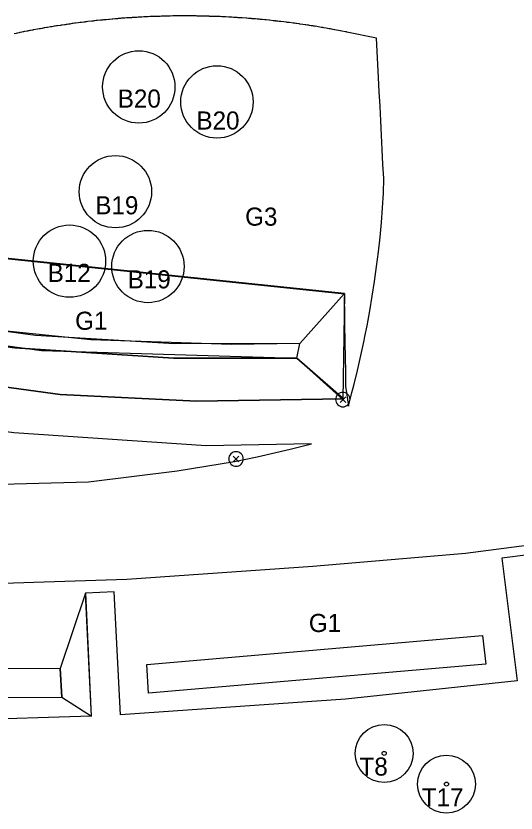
# Model space of a CAD drawing. Extents: x 0 to 512122, y 0 to 6212554.
# Drawn here: x 511565 to 511599.5, y 6211753.4 to 6211808.5 of the extents above; entities that cross this region are included whole.
import ezdxf

# ---------------------------------------------------------------- set-up
doc = ezdxf.new("R2010")
doc.units = 0
for name, color, linetype in [('_lights', 7, 'Continuous'), ('_LØ1', 7, 'Continuous'), ('L40 jord udlagt muld og grøft', 7, 'Continuous'), ('Skel', 7, 'Continuous'), ('TV_U_AFM_Symbl_Gul', 7, 'Continuous'), ('TV_U_LYS_Mastenummer', 7, 'Continuous')]:
    doc.layers.add(name, color=color, linetype=linetype)

# ---------------------------------------------------------------- blocks, each defined once
blk = doc.blocks.new('SOLITAIRE TREES')
at = {"layer": 'Skel'}
for radius in [2, 0.141]:
    blk.add_circle((0, 0), radius, dxfattribs=at)

msp = doc.modelspace()

# ---------------------------------------------------------------- linework, layer by layer
at = {"layer": '_lights'}
for p, q in [((511587.362, 6211782.207), (511587.756, 6211781.813)), ((511587.76, 6211782.211), (511587.366, 6211781.817)), ((511579.978, 6211778.1), (511580.372, 6211777.706)), ((511580.376, 6211778.104), (511579.982, 6211777.71))]:
    msp.add_line(p, q, dxfattribs=at)
for centre, start, end in [((511587.559, 6211782.01), 315.5636, 315), ((511587.559, 6211782.01), 315, 315.5636), ((511580.175, 6211777.903), 315.5636, 315), ((511580.175, 6211777.903), 315, 315.5636)]:
    msp.add_arc(centre, 0.5, start, end, dxfattribs=at)
at = {"layer": '_LØ1'}
msp.add_lwpolyline([(511539.066, 6211784.628), (511539.066, 6211776.31), (511557.102, 6211775.97), (511569.966, 6211776.326), (511576.1, 6211777.084), (511580.076, 6211777.733), (511581.646, 6211778.064), (511583.922, 6211778.583), (511584.736, 6211778.794), (511585.399, 6211778.957), (511578.113, 6211778.822), (511564.816, 6211779.711), (511553.308, 6211781.287), (511544.168, 6211783.234)], close=True, dxfattribs=at)
at = {"layer": 'L40 jord udlagt muld og grøft'}
msp.add_line((511587.73, 6211782.932), (511587.951, 6211781.556), dxfattribs=at)
for points in [[(511585.111, 6211807.892), (511584.999, 6211807.908), (511584.958, 6211807.914), (511584.793, 6211807.938), (511584.577, 6211807.969), (511584.573, 6211807.97), (511584.557, 6211807.972), (511584.519, 6211807.978), (511584.344, 6211808.003), (511584.301, 6211808.009), (511584.213, 6211808.023), (511584.137, 6211808.034), (511584.124, 6211808.036), (511583.86, 6211808.069), (511583.772, 6211808.079), (511583.717, 6211808.085), (511583.668, 6211808.091), (511583.478, 6211808.113), (511583.469, 6211808.114), (511583.279, 6211808.136), (511583.242, 6211808.14), (511583.163, 6211808.149), (511583.065, 6211808.161), (511582.973, 6211808.172), (511582.929, 6211808.177), (511582.929, 6211808.177), (511582.909, 6211808.179), (511582.861, 6211808.185), (511582.76, 6211808.197), (511582.74, 6211808.199), (511582.493, 6211808.228), (511582.489, 6211808.228), (511582.468, 6211808.23), (511582.247, 6211808.251), (511582.176, 6211808.258), (511582.005, 6211808.273), (511582.004, 6211808.273), (511581.96, 6211808.277), (511581.957, 6211808.277), (511581.854, 6211808.286), (511581.772, 6211808.293), (511581.729, 6211808.297), (511581.639, 6211808.305), (511581.512, 6211808.316), (511581.38, 6211808.327), (511581.355, 6211808.329), (511581.268, 6211808.337), (511581.248, 6211808.339), (511581.112, 6211808.35), (511581.097, 6211808.351), (511581.089, 6211808.352), (511581.077, 6211808.353), (511581.035, 6211808.357), (511580.919, 6211808.367), (511580.896, 6211808.369), (511580.877, 6211808.37), (511580.609, 6211808.391), (511580.586, 6211808.392), (511580.585, 6211808.392), (511580.576, 6211808.393), (511580.498, 6211808.397), (511580.381, 6211808.404), (511580.346, 6211808.406), (511580.342, 6211808.406), (511580.335, 6211808.407), (511580.333, 6211808.407), (511580.262, 6211808.411), (511580.068, 6211808.422), (511580.056, 6211808.423), (511580.005, 6211808.425), (511579.884, 6211808.432), (511579.791, 6211808.438), (511579.686, 6211808.444), (511579.472, 6211808.456), (511579.314, 6211808.465), (511579.276, 6211808.467), (511579.192, 6211808.472), (511579.088, 6211808.478), (511579.048, 6211808.48), (511579.037, 6211808.481), (511579.02, 6211808.481), (511578.997, 6211808.482), (511578.987, 6211808.482), (511578.92, 6211808.484), (511578.88, 6211808.485), (511578.769, 6211808.488), (511578.437, 6211808.497), (511578.426, 6211808.497), (511578.336, 6211808.5), (511578.311, 6211808.501), (511578.29, 6211808.501), (511578.276, 6211808.502), (511578.203, 6211808.504), (511578.159, 6211808.505), (511578.15, 6211808.505), (511578.08, 6211808.507), (511578.067, 6211808.507), (511578.001, 6211808.509), (511577.9, 6211808.512), (511577.846, 6211808.513), (511577.746, 6211808.516), (511577.71, 6211808.517), (511577.589, 6211808.52), (511577.516, 6211808.522), (511577.491, 6211808.523), (511577.41, 6211808.525), (511577.259, 6211808.526), (511577.167, 6211808.527), (511577.066, 6211808.527), (511576.943, 6211808.526), (511576.886, 6211808.526), (511576.777, 6211808.526), (511576.729, 6211808.526), (511576.719, 6211808.526), (511576.615, 6211808.525), (511576.561, 6211808.525), (511576.538, 6211808.525), (511576.493, 6211808.525), (511576.439, 6211808.525), (511576.215, 6211808.525), (511576.181, 6211808.525), (511575.89, 6211808.524), (511575.845, 6211808.524), (511575.821, 6211808.524), (511575.806, 6211808.524), (511575.805, 6211808.524), (511575.624, 6211808.522), (511575.583, 6211808.521), (511575.561, 6211808.52), (511575.506, 6211808.518), (511575.493, 6211808.518), (511575.472, 6211808.517), (511575.377, 6211808.514), (511575.163, 6211808.507), (511575.127, 6211808.506), (511575.074, 6211808.504), (511575.025, 6211808.503), (511574.941, 6211808.5), (511574.914, 6211808.5), (511574.908, 6211808.5), (511574.892, 6211808.499), (511574.865, 6211808.498), (511574.76, 6211808.495), (511574.651, 6211808.491), (511574.562, 6211808.488), (511574.432, 6211808.484), (511574.228, 6211808.478), (511574.104, 6211808.474), (511574.046, 6211808.472), (511574.038, 6211808.472), (511573.986, 6211808.469), (511573.859, 6211808.462), (511573.852, 6211808.462), (511573.811, 6211808.459), (511573.669, 6211808.451), (511573.595, 6211808.446), (511573.468, 6211808.438), (511573.429, 6211808.436), (511573.402, 6211808.434), (511573.325, 6211808.43), (511573.1, 6211808.416), (511573.004, 6211808.41), (511572.998, 6211808.41), (511572.937, 6211808.406), (511572.893, 6211808.404), (511572.799, 6211808.398), (511572.728, 6211808.393), (511572.666, 6211808.39), (511572.628, 6211808.387), (511572.623, 6211808.387), (511572.601, 6211808.385), (511572.489, 6211808.378), (511572.47, 6211808.376), (511572.259, 6211808.362), (511572.178, 6211808.355), (511572.104, 6211808.348), (511572.017, 6211808.34), (511571.99, 6211808.338), (511571.973, 6211808.337), (511571.943, 6211808.334), (511571.871, 6211808.327), (511571.825, 6211808.323), (511571.668, 6211808.309), (511571.601, 6211808.303), (511571.429, 6211808.288), (511571.374, 6211808.283), (511571.2, 6211808.267), (511571.163, 6211808.264), (511571.136, 6211808.261), (511571.02, 6211808.251), (511571.013, 6211808.25), (511570.953, 6211808.245), (511570.837, 6211808.234), (511570.802, 6211808.231), (511570.597, 6211808.21), (511570.527, 6211808.202), (511570.514, 6211808.201), (511570.406, 6211808.188), (511570.395, 6211808.187), (511570.375, 6211808.184), (511570.304, 6211808.176), (511570.298, 6211808.175), (511570.227, 6211808.166), (511570.211, 6211808.164), (511569.941, 6211808.132), (511569.845, 6211808.12), (511569.831, 6211808.118), (511569.777, 6211808.112), (511569.727, 6211808.106), (511569.715, 6211808.105), (511569.646, 6211808.096), (511569.501, 6211808.079), (511569.475, 6211808.076), (511569.425, 6211808.07), (511569.412, 6211808.068), (511569.4, 6211808.067), (511569.253, 6211808.049), (511569.073, 6211808.027), (511569.057, 6211808.025), (511569.017, 6211808.02), (511568.892, 6211808.002), (511568.844, 6211807.995), (511568.747, 6211807.981), (511568.676, 6211807.97), (511568.585, 6211807.956), (511568.494, 6211807.942), (511568.43, 6211807.933), (511568.363, 6211807.923), (511568.359, 6211807.922), (511568.306, 6211807.914), (511568.165, 6211807.893), (511568.127, 6211807.887), (511568.092, 6211807.882), (511568.031, 6211807.873), (511567.837, 6211807.844), (511567.766, 6211807.833), (511567.667, 6211807.819), (511567.651, 6211807.816), (511567.629, 6211807.813), (511567.433, 6211807.783), (511567.379, 6211807.774), (511567.356, 6211807.77), (511567.151, 6211807.734), (511567.131, 6211807.731), (511567.09, 6211807.724), (511566.956, 6211807.7), (511566.943, 6211807.698), (511566.933, 6211807.696), (511566.921, 6211807.694), (511566.842, 6211807.68), (511566.762, 6211807.665), (511566.757, 6211807.664), (511566.655, 6211807.646), (511566.574, 6211807.631), (511566.561, 6211807.629), (511566.443, 6211807.607), (511566.191, 6211807.562), (511566.158, 6211807.556), (511566.131, 6211807.552), (511566.115, 6211807.549), (511565.977, 6211807.524), (511565.955, 6211807.52), (511565.926, 6211807.515), (511565.925, 6211807.515), (511565.856, 6211807.502), (511565.801, 6211807.491), (511565.784, 6211807.488), (511565.78, 6211807.487), (511565.764, 6211807.484), (511565.549, 6211807.441), (511565.483, 6211807.428), (511565.465, 6211807.424), (511565.283, 6211807.386), (511565.225, 6211807.374), (511565.177, 6211807.364), (511565.046, 6211807.336), (511564.982, 6211807.323), (511564.843, 6211807.293)], [(511589.89, 6211806.983), (511587.83, 6211807.415), (511587.817, 6211807.418), (511587.803, 6211807.42), (511587.753, 6211807.43), (511587.485, 6211807.486), (511587.392, 6211807.504), (511587.368, 6211807.508), (511587.008, 6211807.575), (511586.991, 6211807.577), (511586.888, 6211807.595), (511586.873, 6211807.598), (511586.769, 6211807.617), (511586.698, 6211807.629), (511586.662, 6211807.636), (511586.625, 6211807.642), (511586.622, 6211807.643), (511586.505, 6211807.663), (511586.409, 6211807.68), (511586.255, 6211807.707), (511586.183, 6211807.72), (511586.076, 6211807.739), (511585.961, 6211807.758), (511585.958, 6211807.759), (511585.757, 6211807.794), (511585.635, 6211807.815), (511585.565, 6211807.825), (511585.529, 6211807.83), (511585.494, 6211807.835), (511585.418, 6211807.846), (511585.377, 6211807.852), (511585.257, 6211807.87), (511585.203, 6211807.878), (511585.111, 6211807.892)], [(511587.951, 6211781.556), (511588.19, 6211782.497), (511588.318, 6211782.993), (511588.572, 6211784.024), (511588.809, 6211785.054), (511589.029, 6211786.083), (511589.088, 6211786.372), (511589.234, 6211787.109), (511589.422, 6211788.134), (511589.595, 6211789.157), (511589.752, 6211790.179), (511589.894, 6211791.199), (511590.02, 6211792.218), (511590.131, 6211793.235), (511590.228, 6211794.25), (511590.31, 6211795.264), (511590.377, 6211796.276), (511590.384, 6211797.282), (511590.333, 6211798.282), (511590.282, 6211799.283), (511590.231, 6211800.283), (511590.181, 6211801.283), (511590.13, 6211802.283), (511590.079, 6211803.283), (511590.028, 6211804.283), (511589.89, 6211806.983)], [(511587.661, 6211789.352), (511553.83, 6211792.863), (511521.099, 6211802.832)], [(511521.1, 6211802.804), (511553.832, 6211792.835), (511587.663, 6211789.324)], [(511518.303, 6211793.584), (511528.762, 6211790.58), (511544.764, 6211786.14), (511553.526, 6211784.336), (511568.012, 6211782.359), (511577.451, 6211781.89), (511587.592, 6211782.058), (511584.385, 6211784.881), (511575.845, 6211784.871), (511564.889, 6211785.591), (511557.457, 6211786.555), (511548.985, 6211788.133), (511542.834, 6211789.608), (511536.487, 6211791.386), (511530.522, 6211793.089), (511521.61, 6211795.629), (511518.303, 6211793.584)], [(511587.663, 6211789.324), (511587.66, 6211788.957), (511587.661, 6211787.951), (511587.673, 6211786.947), (511587.688, 6211786.226), (511587.696, 6211785.944), (511587.728, 6211784.942), (511587.743, 6211783.938), (511587.73, 6211782.932)], [(511600.554, 6211771.296), (511598.553, 6211771.04), (511599.609, 6211762.58), (511587.737, 6211761.296), (511572.192, 6211760.209), (511571.76, 6211768.724), (511569.762, 6211768.633), (511570.165, 6211760.136), (511561.305, 6211759.845), (511553.031, 6211759.792), (511545.838, 6211759.899), (511538.939, 6211760.077), (511539.481, 6211769.281), (511547.52, 6211769.212), (511559.062, 6211769.169), (511572.635, 6211769.6), (511585.486, 6211770.489), (511596.03, 6211771.388), (511605.924, 6211772.694)]]:
    msp.add_lwpolyline(points, dxfattribs=at)
for points in [[(511521.099, 6211802.832), (511553.83, 6211792.863), (511587.661, 6211789.352), (511584.588, 6211785.886), (511575.919, 6211785.865), (511566.312, 6211786.447), (511554.552, 6211788.039), (511541.642, 6211790.936), (511521.868, 6211796.58)], [(511521.868, 6211796.58), (511521.61, 6211795.629), (511542.847, 6211789.604), (511553.476, 6211787.233), (511566.734, 6211785.412), (511584.385, 6211784.881), (511584.587, 6211785.886), (511579.854, 6211785.81), (511570.145, 6211786.138), (511560.037, 6211787.174), (511549.002, 6211789.133), (511533.785, 6211793.174)], [(511521.61, 6211795.629), (511530.522, 6211793.089), (511536.487, 6211791.386), (511542.834, 6211789.608), (511548.985, 6211788.133), (511557.457, 6211786.555), (511564.889, 6211785.591), (511575.845, 6211784.871), (511584.385, 6211784.881), (511587.592, 6211782.058), (511577.451, 6211781.89), (511568.012, 6211782.359), (511553.526, 6211784.336), (511544.764, 6211786.14), (511528.762, 6211790.58), (511518.303, 6211793.584)], [(511587.661, 6211789.352), (511587.559, 6211782.01), (511584.385, 6211784.881), (511584.587, 6211785.886)], [(511569.762, 6211768.633), (511568.023, 6211763.433), (511568.125, 6211761.436), (511570.194, 6211760.118)], [(511597.203, 6211765.711), (511597.45, 6211763.727), (511574.118, 6211761.709), (511574.017, 6211763.707)], [(511542.729, 6211763.379), (511542.663, 6211761.38), (511568.125, 6211761.436), (511568.023, 6211763.433)]]:
    msp.add_lwpolyline(points, close=True, dxfattribs=at)
at = {"layer": 'TV_U_LYS_Mastenummer'}
for centre in [(511573.452, 6211803.619), (511578.857, 6211802.581), (511571.835, 6211796.38), (511568.66, 6211791.579), (511568.66, 6211791.579), (511574.086, 6211791.208), (511574.086, 6211791.208)]:
    msp.add_circle(centre, 2.5, dxfattribs=at)

# ---------------------------------------------------------------- block references
at = {"layer": 'Skel'}
for p in [(511590.415, 6211757.554), (511594.721, 6211755.431)]:
    msp.add_blockref('SOLITAIRE TREES', p, dxfattribs=at)

# ---------------------------------------------------------------- texts
at = {"layer": 'TV_U_AFM_Symbl_Gul'}
for s, p in [('B20', (511572.001, 6211802.191)), ('B20', (511577.44, 6211800.676)), ('B19', (511570.449, 6211794.816)), ('G3', (511580.804, 6211794.031)), ('B12', (511567.155, 6211790.143)), ('B19', (511572.686, 6211789.696)), ('G1', (511569.051, 6211786.834)), ('G1', (511585.207, 6211765.944)), ('T8', (511588.713, 6211756.019)), ('T17', (511593.018, 6211753.896))]:
    msp.add_text(s, height=1.25, dxfattribs=at).set_placement(p)

doc.saveas('drawing.dxf')
